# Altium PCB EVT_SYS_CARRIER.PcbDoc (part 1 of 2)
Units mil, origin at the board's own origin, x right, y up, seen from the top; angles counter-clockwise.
Board outline 3937.01 x 3149.61 mil, 4 copper layers (Top Layer, Mid-Layer 1, Mid-Layer 2, Bottom Layer), stack 63.036 mil thick; 92 components, 67 nets, 529 pads, 132 vias.
Unrouted connection lines stored in the file: 166.
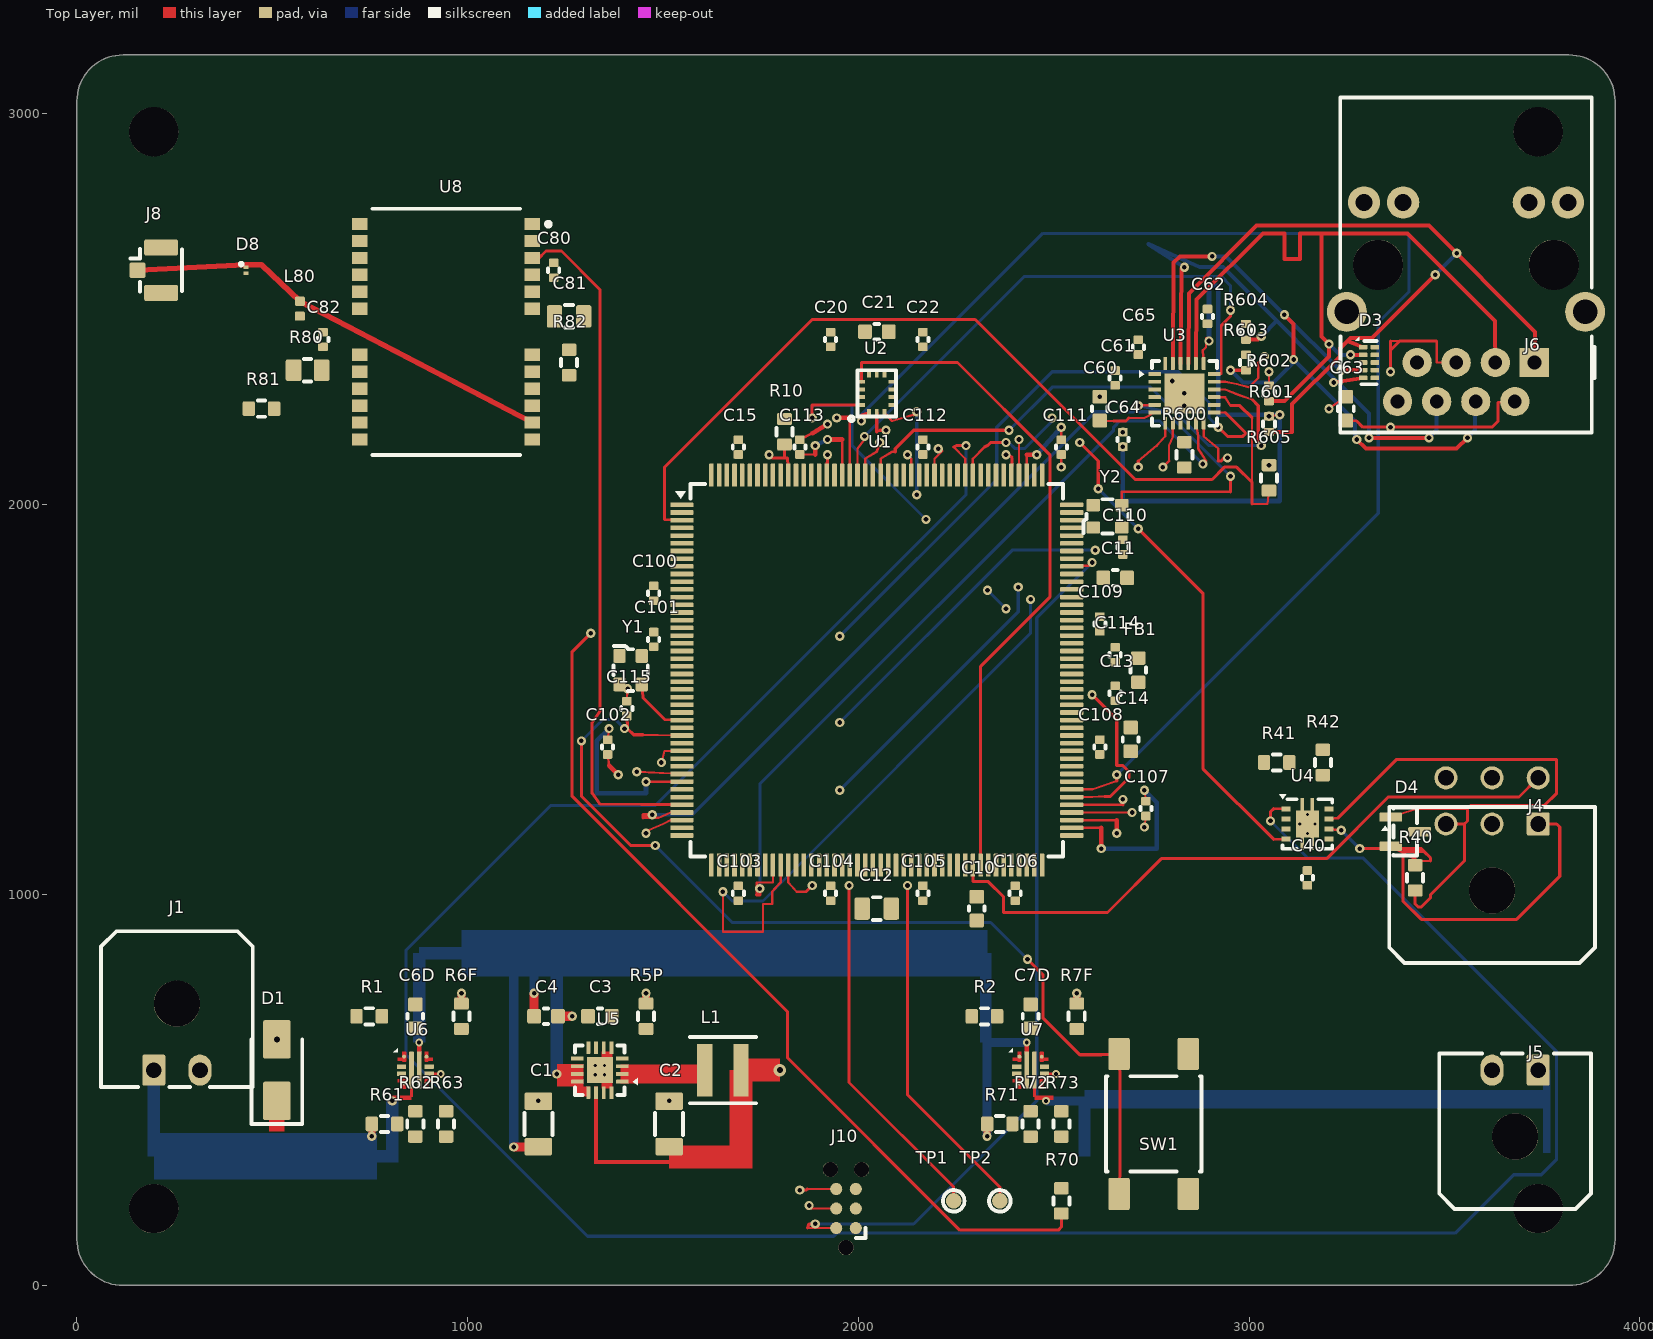
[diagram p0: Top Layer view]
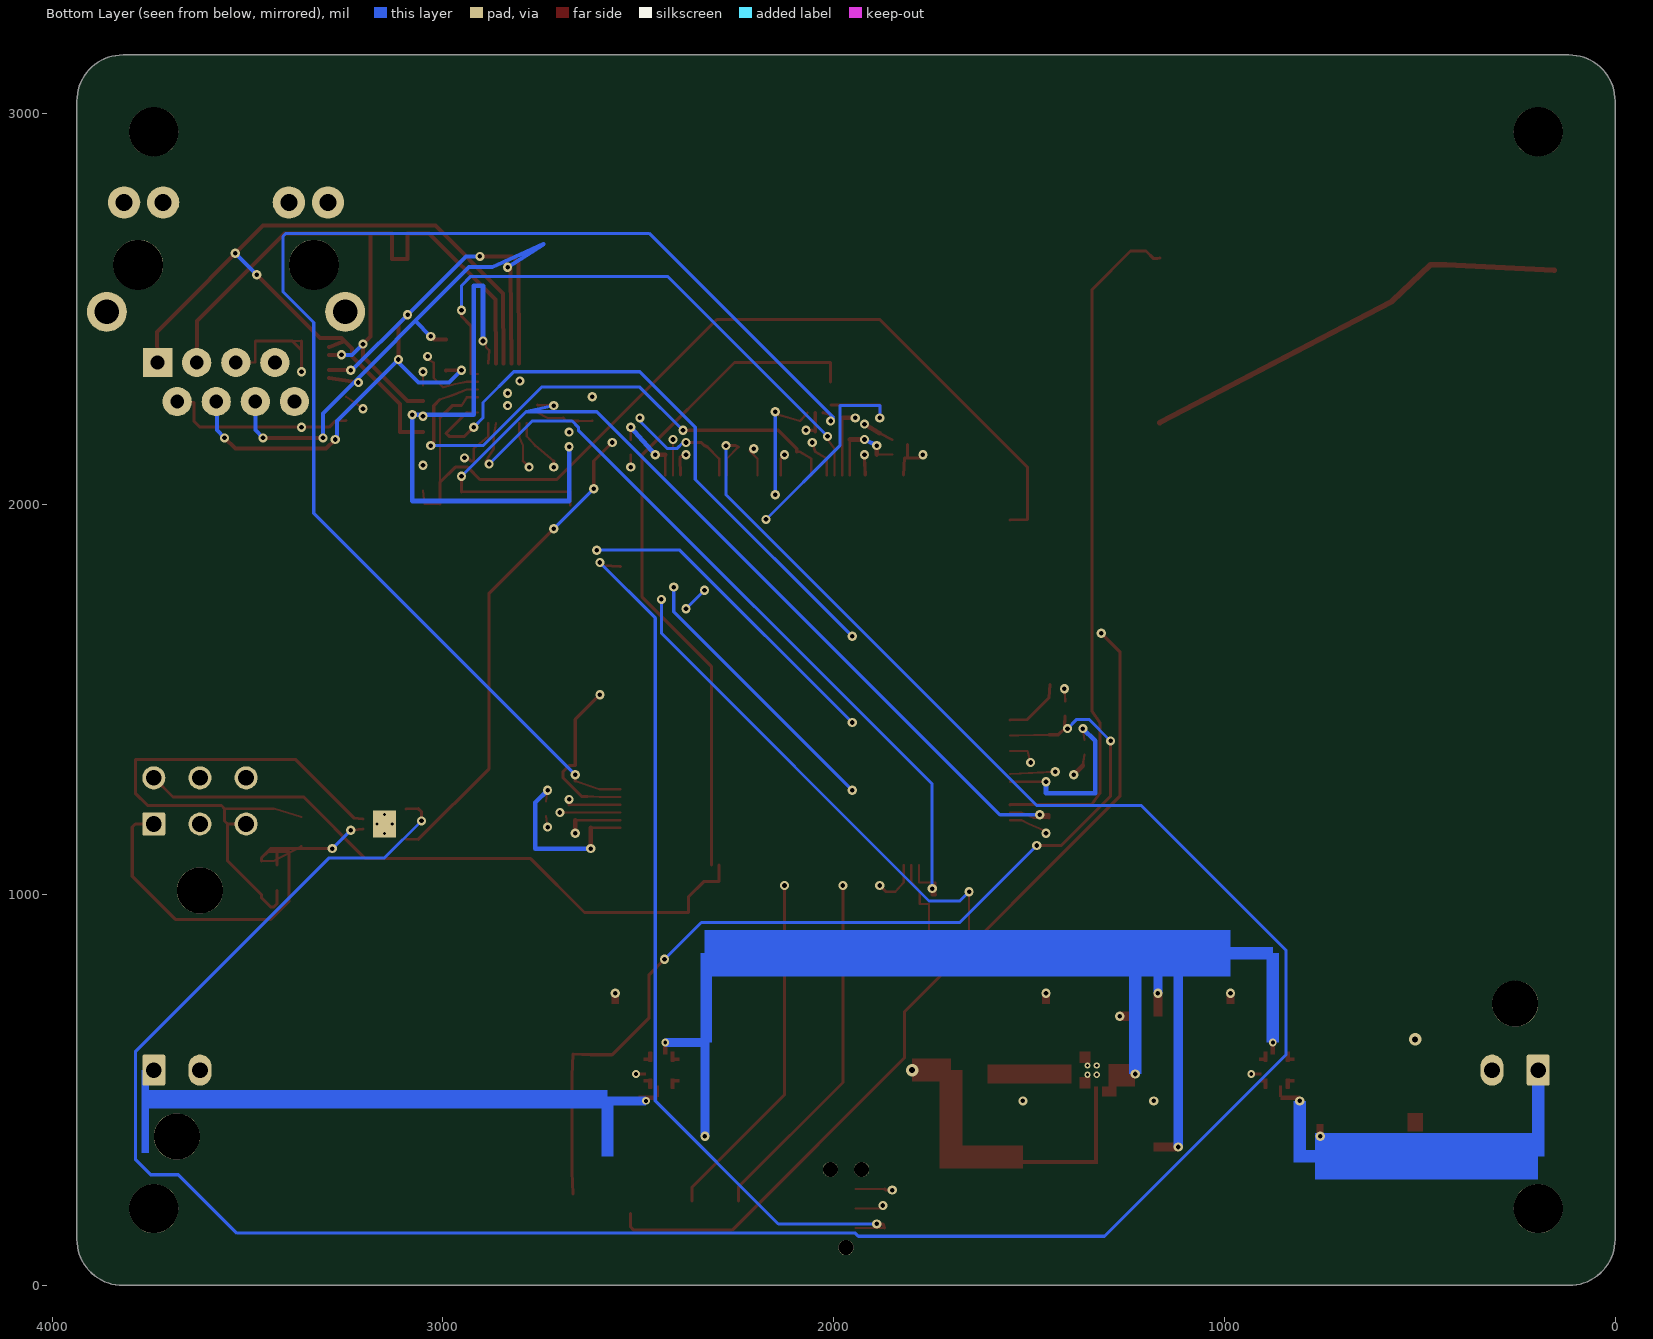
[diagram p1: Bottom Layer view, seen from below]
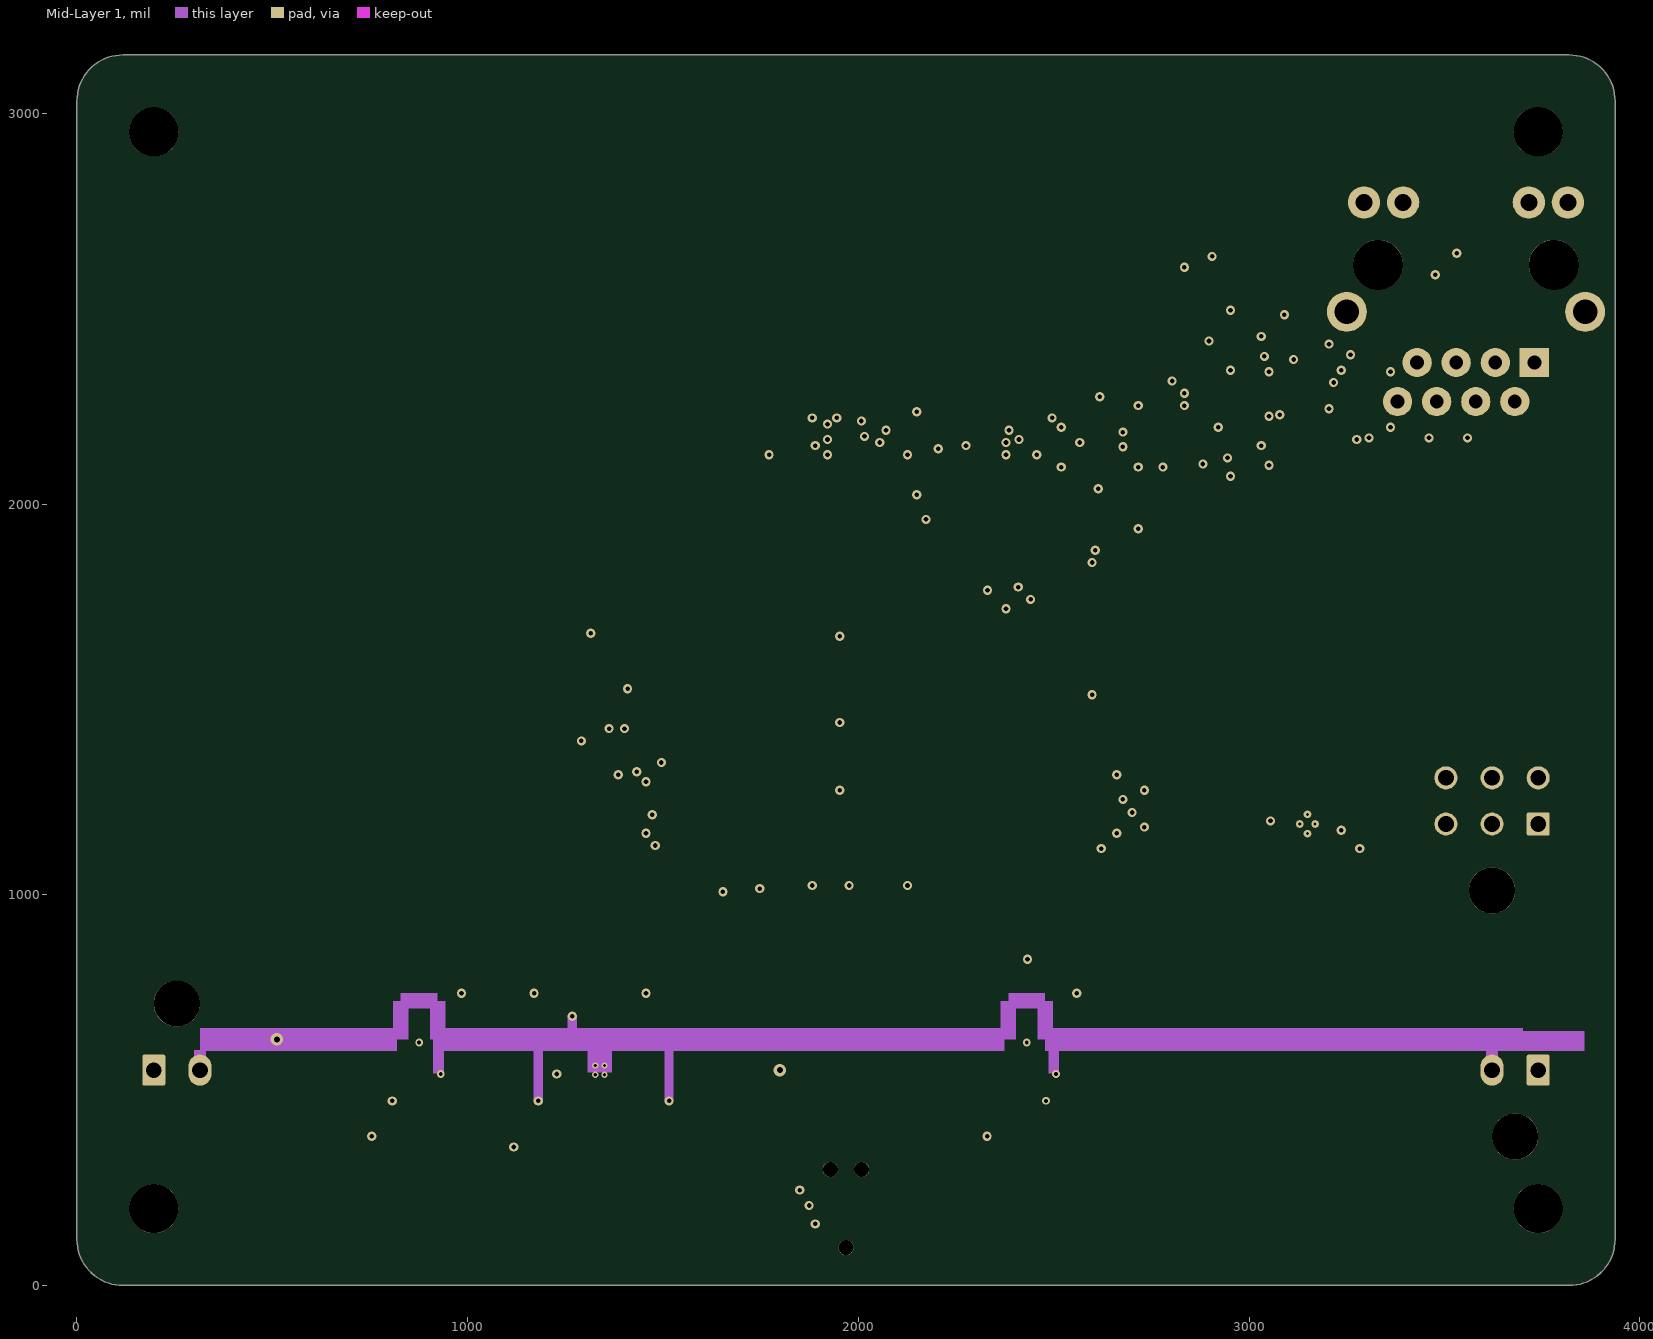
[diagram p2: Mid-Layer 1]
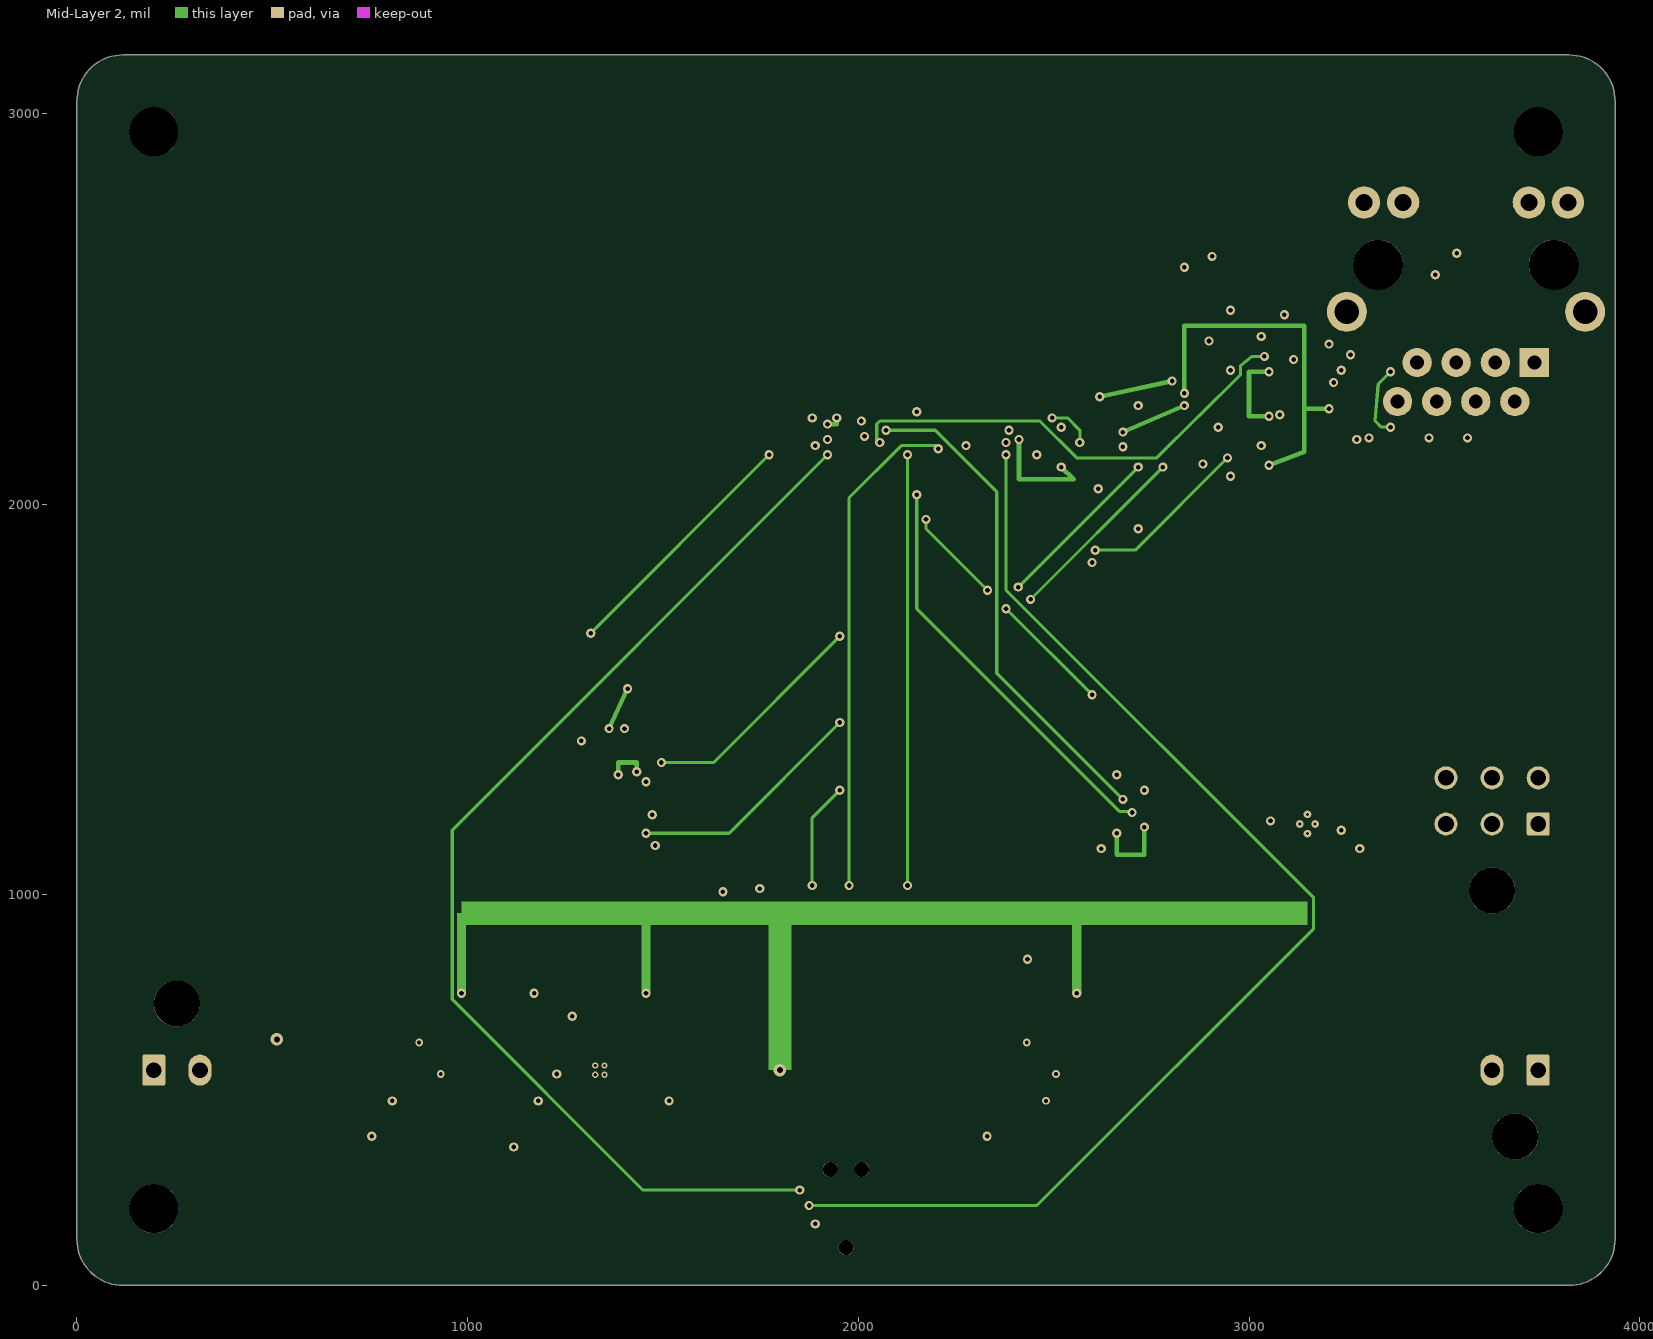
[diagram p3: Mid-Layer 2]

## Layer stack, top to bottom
Top Solder: solder mask 0.4, Solder Resist, Dk 3.5
Top Layer: signal copper 1.4
Dielectric 2: prepreg 7.0866, PP-006, Dk 4.2
Mid-Layer 1: signal copper 1.378
Dielectric 1: dielectric 43.3071, FR-4, Dk 4.2
Mid-Layer 2: signal copper 1.378
Dielectric 3: prepreg 7.0866, PP-006, Dk 4.2
Bottom Layer: signal copper 1.4
Bottom Solder: solder mask 0.4, Solder Resist, Dk 3.5

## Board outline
118.11,0 cw(c118.11,118.11) 0,118.11 0,3031.5 cw(c118.11,3031.5) 118.11,3149.61 3818.9,3149.61 cw(c3818.9,3031.5) 3937.01,3031.5 3937.01,118.11 cw(c3818.9,118.11) 3818.9,0

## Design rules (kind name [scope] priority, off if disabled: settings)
Clearance R_FINE_PITCH_CLEARANCE [(InComponent('U6') Or InComponent('U7') Or InComponent('D8')) vs (InComponent('U6') Or InComponent('U7') Or InComponent('D8'))] p1: gap=5.12 ignorepadtopadclearanceinfootprint=FALSE // Footprint-defined fine-pitch clearance; fabricator confirmation deferred
Clearance R_TIMING_TO_SW_CLEARANCE [InNetClass('NC_TIMING') vs InNet('BUCK_SW')] p2: gap=39.37 ignorepadtopadclearanceinfootprint=FALSE // EVT routing contract
Clearance R_ETH_MDI_CLEARANCE [InDifferentialPairClass('DP_ETH_MDI') vs Not InDifferentialPairClass('DP_ETH_MDI')] p3: gap=7.87 ignorepadtopadclearanceinfootprint=FALSE // EVT routing contract
Clearance R_GENERAL_CLEARANCE [All] p4: gap=7.87 ignorepadtopadclearanceinfootprint=FALSE // EVT routing contract
Clearance [All] p5: gap=10 ignorepadtopadclearanceinfootprint=FALSE
ComponentClearance [All] p1 off: gap=7.87 collisioncheckmode=3 verticalgap=7.87 showdistances=FALSE // Disabled: imported body extents are not assembly courtyards; see placement review evidence
DiffPairsRouting R_CAN_DIFF [InDifferentialPairClass('DP_CAN')] p1: maxlimit=11.81 minlimit=7.87 mostfreqgap=7.87 toplayer_minwidth=7.87 toplayer_maxwidth=11.81 toplayer_prefwidth=7.87 midlayer1_minwidth=7.87 midlayer1_maxwidth=11.81 midlayer1_prefwidth=7.87 midlayer2_minwidth=7.87 midlayer2_maxwidth=11.81 midlayer2_prefwidth=7.87 bottomlayer_minwidth=7.87 bottomlayer_maxwidth=11.81 bottomlayer_prefwidth=7.87 maxuncoupledlength=500 // EVT routing contract
DiffPairsRouting R_ETH_MDI_DIFF [InDifferentialPairClass('DP_ETH_MDI')] p2: maxlimit=7.87 minlimit=7.87 mostfreqgap=7.87 toplayer_minwidth=10.24 toplayer_maxwidth=10.24 toplayer_prefwidth=10.24 midlayer1_minwidth=10.24 midlayer1_maxwidth=10.24 midlayer1_prefwidth=10.24 midlayer2_minwidth=10.24 midlayer2_maxwidth=10.24 midlayer2_prefwidth=10.24 bottomlayer_minwidth=10.24 bottomlayer_maxwidth=10.24 bottomlayer_prefwidth=10.24 maxuncoupledlength=500 // EVT routing contract
DiffPairsRouting [All] p3: maxlimit=10 minlimit=10 mostfreqgap=10 toplayer_minwidth=15 toplayer_maxwidth=15 toplayer_prefwidth=15 midlayer1_minwidth=15 midlayer1_maxwidth=15 midlayer1_prefwidth=15 midlayer2_minwidth=15 midlayer2_maxwidth=15 midlayer2_prefwidth=15 bottomlayer_minwidth=15 bottomlayer_maxwidth=15 bottomlayer_prefwidth=15 maxuncoupledlength=500
HoleSize [All] p1: absolutevalues=TRUE maxlimit=129.92 minlimit=7.09 maxpercent=80.000 minpercent=20.000 // Standard PTH and 3.2/3.25mm mechanical holes
PolygonConnect [All] p1: connectstyle=Relief reliefconductorwidth=10 reliefentries=4 polygonreliefangle="90 Angle" airgapwidth=10
RoutingVias [All] p1: holewidth=28 width=50 viastyle="Through Hole" minholewidth=28 minwidth=50 maxholewidth=28 maxwidth=50
SolderMaskExpansion [All] p1: expansion=0 istentingtop=FALSE
Width R_3V3_TRUNK_WIDTH [InNet('3V3')] p1: maxlimit=118.11 minlimit=59.06 preferedwidth=59.06 // EVT routing contract
Width R_RADAR_12V_WIDTH [InNet('RADAR_12V')] p2: maxlimit=118.11 minlimit=59.06 preferedwidth=59.06
Width R_VIN_HIGH_CURRENT [InNet('VIN_RAW','VIN_PROTECTED')] p3: maxlimit=196.85 minlimit=118.11 preferedwidth=118.11
Width R_GNSS_RF_WIDTH [InNet('GNSS_RF')] p4: maxlimit=14.17 minlimit=14.17 preferedwidth=14.17
Width R_GENERAL_WIDTH [All] p5: maxlimit=19.68 minlimit=5.91 preferedwidth=7.87
27 further rules are at their usual default settings.

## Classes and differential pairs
net class NC_IMU_SPI: IMU_MISO IMU_MOSI IMU_NSS IMU_SCK
net class NC_RMII: ETH_50M ETH_CRS_DV ETH_MDC ETH_MDIO ETH_NRST ETH_RXD0 ETH_RXD1 ETH_TX_EN ETH_TXD0 ETH_TXD1
net class NC_TIMING: GNSS_PPS IMU_DRDY RADAR_REF
net class NC_CAN: RADAR_CANH RADAR_CANL
net class NC_GNSS_RF: GNSS_RF
net class NC_ETH_MDI: ETH_RXN ETH_RXP ETH_TXN ETH_TXP
net class NC_POWER_3V3: 3V3 VDDA_FILTERED
net class NC_POWER_12V: RADAR_12V VIN_PROTECTED VIN_RAW
differential pair class DP_CAN: DP_CAN
differential pair class DP_ETH_MDI: DP_ETH_RX DP_ETH_TX
component class 70_DEBUG_BOOT: R70 SW1
component class 60_ETHERNET: C60 C61 C62 C63 C64 C65 D3 J6 R600 R601 R602 R603 R604 R605 U3 Y2
component class 50_RADAR_IO_CAN: C40 D4 J4 J5 R40 R41 R42 U4
component class 40_IMU: C20 C21 C22 U2
component class 30_TIME_GNSS: C80 C81 C82 D8 J8 L80 R80 R81 R82 U8
component class 20_MCU_CORE: C10 C11 C12 C13 C14 C15 C100 C101 C102 C103 C104 C105 C106 C107 C108 C109 C110 C111 C112 C113 C114 C115 FB1 J10 R10 TP1 TP2 U1 Y1
component class 10_POWER_INPUT: C1 C2 C3 C4 C6D C7D D1 J1 L1 R1 R2 R5P R6F R7F R61 R62 R63 R71 R72 R73 U5 U6 U7
differential pair DP_CAN: +RADAR_CANH -RADAR_CANL
differential pair DP_ETH_RX: +ETH_RXP -ETH_RXN
differential pair DP_ETH_TX: +ETH_TXP -ETH_TXN

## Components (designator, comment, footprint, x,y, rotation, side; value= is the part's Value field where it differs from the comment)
C1 "10uF/25V" C_1206_3216Metric 1181.1,413.39 r90 top
C2 "22uF/6.3V" C_1206_3216Metric 1515.75,413.39 r90 top
C3 "3.3nF" C_0603_1608Metric 1338.58,688.98 r0 top
C4 "100nF/25V" C_0603_1608Metric 1200.79,688.98 r0 top
C6D "3.3nF" C_0603_1608Metric 866.14,688.98 r90 top
C7D "3.3nF" C_0603_1608Metric 2440.94,688.98 r90 top
C10 "2.2uF" C_0603_1608Metric 2303.15,964.57 r90 top
C11 "2.2uF" C_0603_1608Metric 2657.48,1811.02 r0 top
C12 "4.7uF" C_0805_2012Metric 2047.24,964.57 r0 top
C13 "100nF" C_0402_1005Metric 2657.48,1515.75 r90 top
C14 "1uF" C_0603_1608Metric 2696.85,1397.64 r90 top
C15 "100nF" C_0402_1005Metric 1692.91,2145.67 r90 top
C20 "100nF" C_0402_1005Metric 1929.13,2421.26 r90 top
C21 "2.2uF" C_0603_1608Metric 2047.24,2440.94 r0 top
C22 "10nF" C_0402_1005Metric 2165.35,2421.26 r90 top
C40 "100nF" C_0402_1005Metric 3149.61,1043.31 r90 top
C60 "1uF" C_0603_1608Metric 2618.11,2244.09 r90 top
C61 "470pF C0G" C_0402_1005Metric 2657.48,2322.83 r90 top
C62 "100nF" C_0402_1005Metric 2893.7,2480.32 r90 top
C63 "22nF C0G" C_0603_1608Metric 3248.03,2244.09 r90 top
C64 "100nF" C_0402_1005Metric 2677.16,2165.35 r90 top
C65 "100nF" C_0402_1005Metric 2716.54,2401.57 r90 top
C80 "100nF" C_0402_1005Metric 1220.47,2598.43 r90 top
C81 "10uF" C_0805_2012Metric 1259.84,2480.32 r0 top
C82 "100nF DNP_OPTION" C_0402_1005Metric 629.92,2421.26 r90 top
C100 "100nF VDD" C_0402_1005Metric 1476.38,1771.65 r90 top
C101 "100nF VDD" C_0402_1005Metric 1476.38,1653.54 r90 top
C102 "100nF VDD" C_0402_1005Metric 1358.27,1377.95 r90 top
C103 "100nF VDD" C_0402_1005Metric 1692.91,1003.94 r90 top
C104 "100nF VDD" C_0402_1005Metric 1929.13,1003.94 r90 top
C105 "100nF VDD" C_0402_1005Metric 2165.35,1003.94 r90 top
C106 "100nF VDD" C_0402_1005Metric 2401.57,1003.94 r90 top
C107 "100nF VDD" C_0402_1005Metric 2736.22,1220.47 r90 top
C108 "100nF VDD" C_0402_1005Metric 2618.11,1377.95 r90 top
C109 "100nF VDD" C_0402_1005Metric 2618.11,1692.91 r90 top
C110 "100nF VDD" C_0402_1005Metric 2677.17,1889.76 r90 top
C111 "100nF VDD" C_0402_1005Metric 2519.69,2145.67 r90 top
C112 "100nF VDD" C_0402_1005Metric 2165.35,2145.67 r90 top
C113 "100nF VDD" C_0402_1005Metric 1850.39,2145.67 r90 top
C114 "100nF VDD33_USB" C_0402_1005Metric 2657.48,1614.17 r90 top
C115 "100nF NRST" C_0402_1005Metric 1407.48,1476.38 r90 top
D1 "SMAJ15CA" D_SMA 511.81,551.18 r90 top
D3 "TPD4E05U06DQAR" USON-10_2.5x1.0mm_P0.5mm 3307.09,2362.2 r0 top
D4 "ESD2CANFD24-Q1" SOT-23 3399.61,1161.42 r0 top
D8 "ESD0P2RF-02LS" ESD0P2RF-02LS_PG-TSSLP-2-1 433.07,2598.43 r0 top
FB1 "BLM18BD601SH1" L_0603_1608Metric 2716.54,1574.8 r90 top
J1 "12V_IN" Molex_43650-0200_RA_THT_2P#1 196.85,551.18 r0 top
J4 "RADAR_IO" Molex_43045-0600_RA_THT_6P 3740.16,1181.1 r180 top
J5 "RADAR_PWR" Molex_43650-0200_RA_THT_2P#2 3740.16,551.18 r180 top
J6 "SI-60182-F" RJ45_Bel_SI-60062-F 3730.32,2362.2 r180 top
J8 "GNSS_UFL" Hirose_UFL_R_SMT_K 196.85,2598.43 r0 top
J10 "TC2030_SWD" TagConnect_TC2030_NL 1968.5,196.85 r90 top
L1 "2.2uH" Coilcraft_XFL4020_4x4 1653.54,551.18 r0 top
L80 "27nH DNP_OPTION" L_0402_1005Metric 570.87,2500 r90 top
R1 "665R 1%" R_0603_1608Metric 748.03,688.98 r0 top
R2 "1.05k 1%" R_0603_1608Metric 2322.83,688.98 r0 top
R5P "100k 1% PG_PU" R_0603_1608Metric 1456.69,688.98 r90 top
R6F "10k 1% FLT_PU" R_0603_1608Metric 984.25,688.98 r90 top
R7F "10k 1% FLT_PU" R_0603_1608Metric 2559.06,688.98 r90 top
R10 "10k 1%" R_0603_1608Metric 1811.02,2185.04 r90 top
R40 "120R 1% DNP_DEFAULT" R_0603_1608Metric 3425.2,1043.31 r90 top
R41 "10k 1% STB_PD" R_0603_1608Metric 3070.87,1338.58 r0 top
R42 "10k 1% SHDN_PD" R_0603_1608Metric 3188.98,1338.58 r90 top
R61 "470k 1%" R_0603_1608Metric 787.4,413.39 r0 top
R62 "36.0k 1%" R_0603_1608Metric 866.14,413.39 r90 top
R63 "41.2k 1%" R_0603_1608Metric 944.88,413.39 r90 top
R70 "0R DNP_BOOT_OVERRIDE" R_0603_1608Metric 2519.68,216.54 r90 top
R71 "470k 1%" R_0603_1608Metric 2362.2,413.39 r0 top
R72 "16.9k 1%" R_0603_1608Metric 2440.94,413.39 r90 top
R73 "43.7k 1%" R_0603_1608Metric 2519.68,413.39 r90 top
R80 "10R 0.25W DNP_OPTION" R_0805_2012Metric 590.55,2342.52 r0 top
R81 "100k 1% VUSB_PD" R_0603_1608Metric 472.44,2244.09 r0 top
R82 "0R V_BCKP" R_0603_1608Metric 1259.84,2362.2 r90 top
R600 "12.1k 1%" R_0603_1608Metric 2834.65,2125.98 r90 top
R601 "49.9R 1%" R_0402_1005Metric 3051.18,2204.72 r90 top
R602 "49.9R 1%" R_0402_1005Metric 3051.18,2283.47 r90 top
R603 "49.9R 1%" R_0402_1005Metric 2992.13,2362.2 r90 top
R604 "49.9R 1%" R_0402_1005Metric 2992.13,2440.94 r90 top
R605 "10k 1% NRST_PD" R_0603_1608Metric 3051.18,2066.93 r90 top
SW1 "NRST" ESwitch_TL3301_GullWing_6x6 2755.91,314.96 r90 top
TP1 "DEBUG_TX" TestPoint_Pad_D1.0mm 2244.09,216.54 r0 top
TP2 "DEBUG_RX" TestPoint_Pad_D1.0mm 2362.2,216.54 r0 top
U1 "STM32H753IIT6" LQFP-176_24x24mm_P0.5mm 2047.24,1574.8 r0 top
U2 "ICM-42688-P" ICM-42688-P_LGA14_2.5x3mm_P0.5mm 2047.24,2283.46 r0 top
U3 "LAN8742Ai-CZ-TR" QFN-24-1EP_4x4mm_P0.5mm_EP2.6x2.6mm 2834.65,2283.46 r0 top
U4 "TCAN3404DRBRQ1" Texas_DRB0008A 3149.61,1181.1 r0 top
U5 "TPS62132RGTR_3V3" VQFN-16-1EP_3x3mm_P0.5mm_EP1.68x1.68mm 1338.58,551.18 r180 top
U6 "TPS259470ARPWR_SYS" TPS259470A_RPW0010A_VQFN-HR-10_2x2mm_P0.475mm 866.14,551.18 r0 top
U7 "TPS259470ARPWR_RADAR" TPS259470A_RPW0010A_VQFN-HR-10_2x2mm_P0.475mm 2440.94,551.18 r0 top
U8 "NEO-M9N-00B" NEO-M9N_LCC24_12.2x16mm 944.88,2440.94 r0 top
Y1 "ECS-2520S33-250-FN-TR" Oscillator_SMD_ECS_2520MV-xxx-xx-4Pin_2.5x2.0mm 1417.32,1574.8 r0 top
Y2 "ECS-2520S33-500-FN-TR" Oscillator_SMD_ECS_2520MV-xxx-xx-4Pin_2.5x2.0mm 2637.8,1968.5 r90 top

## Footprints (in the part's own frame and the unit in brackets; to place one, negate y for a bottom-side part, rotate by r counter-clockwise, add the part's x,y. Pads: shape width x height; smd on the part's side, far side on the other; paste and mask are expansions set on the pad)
C_0402_1005Metric [mm]
  rrect25% 0.56x0.62 smd: 1(-0.48,0) 2(0.48,0)
  silkscreen extent -0.11,-0.36 0.11,0.36
C_0603_1608Metric [mm]
  rrect25% 0.9x0.95 smd: 1(-0.775,0) 2(0.775,0)
  silkscreen extent -0.14,-0.51 0.14,0.51
C_0805_2012Metric [mm]
  rrect25% 1x1.45 smd: 1(-0.95,0) 2(0.95,0)
  silkscreen extent -0.26,-0.73 0.26,0.73
C_1206_3216Metric [mm]
  rrect22% 1.15x1.8 smd: 1(-1.475,0) 2(1.475,0)
  silkscreen extent -0.71,-0.91 0.71,0.91
Coilcraft_XFL4020_4x4 [mm]
  rect 0.98x3.4 smd: 1(-1.185,0) 2(1.185,0)
  silkscreen extent -2.15,-2.15 2.15,2.15
D_SMA [mm]
  rrect14% 2.5x1.8 smd: 1(-2,0) 2(2,0)
  silkscreen extent -3.51,-1.65 2,1.65
ESD0P2RF-02LS_PG-TSSLP-2-1 [mm]
  rect 0.32x0.24 smd: 1(0,0.19) 2(0,-0.19)
  silkscreen extent -0.4,0.32 -0.24,0.48
ESwitch_TL3301_GullWing_6x6 [mil]
Hirose_UFL_R_SMT_K [mm]
  rrect25% 1.05x1 smd: 1(-1.05,0)
  rrect24% 2.2x1.05 smd: 2(0.475,-1.475) 2(0.475,1.475)
  silkscreen extent -1.52,-1.4 1.84,1.4
ICM-42688-P_LGA14_2.5x3mm_P0.5mm [mm]
  rect 0.475x0.25 smd: 1(-1.012,-0.75) 2(-1.012,-0.25) 3(-1.012,0.25) 4(-1.012,0.75) 8(1.012,0.75) 9(1.012,0.25) 10(1.012,-0.25) 11(1.012,-0.75)
  rect 0.25x0.475 smd: 5(-0.5,1.262) 6(0,1.262) 7(0.5,1.262) 12(0.5,-1.262) 13(0,-1.262) 14(-0.5,-1.262)
  silkscreen extent -1.8,-1.8 1.25,1.5
L_0402_1005Metric [mm]
  rrect25% 0.59x0.64 smd: 1(-0.485,0) 2(0.485,0)
L_0603_1608Metric [mm]
  rrect25% 0.875x0.95 smd: 1(-0.787,0) 2(0.787,0)
  silkscreen extent -0.16,-0.51 0.16,0.51
LQFP-176_24x24mm_P0.5mm [mm]
  rrect25% 1.5x0.3 smd: 1(-12.675,10.75) 2(-12.675,10.25) 3(-12.675,9.75) 4(-12.675,9.25) 5(-12.675,8.75) 6(-12.675,8.25) 7(-12.675,7.75) 8(-12.675,7.25) 9(-12.675,6.75) 10(-12.675,6.25) 11(-12.675,5.75) 12(-12.675,5.25) 13(-12.675,4.75) 14(-12.675,4.25) 15(-12.675,3.75) 16(-12.675,3.25) 17(-12.675,2.75) 18(-12.675,2.25) 19(-12.675,1.75) 20(-12.675,1.25) 21(-12.675,0.75) 22(-12.675,0.25) 23(-12.675,-0.25) 24(-12.675,-0.75) 25(-12.675,-1.25) 26(-12.675,-1.75) 27(-12.675,-2.25) 28(-12.675,-2.75) 29(-12.675,-3.25) 30(-12.675,-3.75) 31(-12.675,-4.25) 32(-12.675,-4.75) 33(-12.675,-5.25) 34(-12.675,-5.75) 35(-12.675,-6.25) 36(-12.675,-6.75) 37(-12.675,-7.25) 38(-12.675,-7.75) 39(-12.675,-8.25) 40(-12.675,-8.75) 41(-12.675,-9.25) 42(-12.675,-9.75) 43(-12.675,-10.25) 44(-12.675,-10.75) 89(12.675,-10.75) 90(12.675,-10.25) 91(12.675,-9.75) 92(12.675,-9.25) 93(12.675,-8.75) 94(12.675,-8.25) 95(12.675,-7.75) 96(12.675,-7.25) 97(12.675,-6.75) 98(12.675,-6.25) 99(12.675,-5.75) 100(12.675,-5.25) 101(12.675,-4.75) 102(12.675,-4.25) 103(12.675,-3.75) 104(12.675,-3.25) 105(12.675,-2.75) 106(12.675,-2.25) 107(12.675,-1.75) 108(12.675,-1.25) 109(12.675,-0.75) 110(12.675,-0.25) 111(12.675,0.25) 112(12.675,0.75) 113(12.675,1.25) 114(12.675,1.75) 115(12.675,2.25) 116(12.675,2.75) 117(12.675,3.25) 118(12.675,3.75) 119(12.675,4.25) 120(12.675,4.75) 121(12.675,5.25) 122(12.675,5.75) 123(12.675,6.25) 124(12.675,6.75) 125(12.675,7.25) 126(12.675,7.75) 127(12.675,8.25) 128(12.675,8.75) 129(12.675,9.25) 130(12.675,9.75) 131(12.675,10.25) 132(12.675,10.75)
  rrect25% 0.3x1.5 smd: 45(-10.75,-12.675) 46(-10.25,-12.675) 47(-9.75,-12.675) 48(-9.25,-12.675) 49(-8.75,-12.675) 50(-8.25,-12.675) 51(-7.75,-12.675) 52(-7.25,-12.675) 53(-6.75,-12.675) 54(-6.25,-12.675) 55(-5.75,-12.675) 56(-5.25,-12.675) 57(-4.75,-12.675) 58(-4.25,-12.675) 59(-3.75,-12.675) 60(-3.25,-12.675) 61(-2.75,-12.675) 62(-2.25,-12.675) 63(-1.75,-12.675) 64(-1.25,-12.675) 65(-0.75,-12.675) 66(-0.25,-12.675) 67(0.25,-12.675) 68(0.75,-12.675) 69(1.25,-12.675) 70(1.75,-12.675) 71(2.25,-12.675) 72(2.75,-12.675) 73(3.25,-12.675) 74(3.75,-12.675) 75(4.25,-12.675) 76(4.75,-12.675) 77(5.25,-12.675) 78(5.75,-12.675) 79(6.25,-12.675) 80(6.75,-12.675) 81(7.25,-12.675) 82(7.75,-12.675) 83(8.25,-12.675) 84(8.75,-12.675) 85(9.25,-12.675) 86(9.75,-12.675) 87(10.25,-12.675) 88(10.75,-12.675) 133(10.75,12.675) 134(10.25,12.675) 135(9.75,12.675) 136(9.25,12.675) 137(8.75,12.675) 138(8.25,12.675) 139(7.75,12.675) 140(7.25,12.675) 141(6.75,12.675) 142(6.25,12.675) 143(5.75,12.675) 144(5.25,12.675) 145(4.75,12.675) 146(4.25,12.675) 147(3.75,12.675) 148(3.25,12.675) 149(2.75,12.675) 150(2.25,12.675) 151(1.75,12.675) 152(1.25,12.675) 153(0.75,12.675) 154(0.25,12.675) 155(-0.25,12.675) 156(-0.75,12.675) 157(-1.25,12.675) 158(-1.75,12.675) 159(-2.25,12.675) 160(-2.75,12.675) 161(-3.25,12.675) 162(-3.75,12.675) 163(-4.25,12.675) 164(-4.75,12.675) 165(-5.25,12.675) 166(-5.75,12.675) 167(-6.25,12.675) 168(-6.75,12.675) 169(-7.25,12.675) 170(-7.75,12.675) 171(-8.25,12.675) 172(-8.75,12.675) 173(-9.25,12.675) 174(-9.75,12.675) 175(-10.25,12.675) 176(-10.75,12.675)
  silkscreen extent -13.09,-12.11 12.11,12.11
Molex_43045-0600_RA_THT_6P [mil]
Molex_43650-0200_RA_THT_2P#1 [mm]
  rrect17% 1.5x2.02 hole 1.02: 1(0,0)
  rrect100% 1.5x2.02 hole 1.02: 2(3,0)
  round 3 hole 3: Un1(1.5,4.32)
  silkscreen extent -3.43,-1.09 6.44,9.03
Molex_43650-0200_RA_THT_2P#2 [mm]
NEO-M9N_LCC24_12.2x16mm [mm]
  rect 1x0.8 smd: 1(5.6,7) 2(5.6,5.9) 3(5.6,4.8) 4(5.6,3.7) 5(5.6,2.6) 6(5.6,1.5) 7(5.6,-1.5) 8(5.6,-2.6) 9(5.6,-3.7) 10(5.6,-4.8) 11(5.6,-5.9) 12(5.6,-7) 13(-5.6,-7) 14(-5.6,-5.9) 15(-5.6,-4.8) 16(-5.6,-3.7) 17(-5.6,-2.6) 18(-5.6,-1.5) 19(-5.6,1.5) 20(-5.6,2.6) 21(-5.6,3.7) 22(-5.6,4.8) 23(-5.6,5.9) 24(-5.6,7)
  silkscreen extent -4.8,-8 6.8,8
Oscillator_SMD_ECS_2520MV-xxx-xx-4Pin_2.5x2.0mm [mm]
  rrect25% 0.8x0.9 smd: 1(-0.725,0.925) 2(-0.725,-0.925) 3(0.725,-0.925) 4(0.725,0.925)
  silkscreen extent -1.11,-1.36 1.11,1.56
QFN-24-1EP_4x4mm_P0.5mm_EP2.6x2.6mm [mm]
  rrect25% 0.825x0.25 smd: 1(-1.937,1.25) 2(-1.937,0.75) 3(-1.937,0.25) 4(-1.937,-0.25) 5(-1.937,-0.75) 6(-1.937,-1.25) 13(1.937,-1.25) 14(1.937,-0.75) 15(1.937,-0.25) 16(1.937,0.25) 17(1.937,0.75) 18(1.937,1.25)
  rrect25% 0.25x0.825 smd: 7(-1.25,-1.937) 8(-0.75,-1.937) 9(-0.25,-1.937) 10(0.25,-1.937) 11(0.75,-1.937) 12(1.25,-1.937) 19(1.25,1.937) 20(0.75,1.937) 21(0.25,1.937) 22(-0.25,1.937) 23(-0.75,1.937) 24(-1.25,1.937)
  rect 2.6x2.6 smd: 25(0,0)
  rrect24% 1.05x1.05 on Top Paste: Un1(-0.65,0.65) Un2(-0.65,-0.65) Un3(0.65,0.65) Un4(0.65,-0.65)
  silkscreen extent -2.94,-2.11 2.11,2.11
R_0402_1005Metric [mm]
  rrect25% 0.54x0.64 smd: 1(-0.51,0) 2(0.51,0)
  silkscreen extent -0.15,-0.38 0.15,0.38
R_0603_1608Metric [mm]
  rrect25% 0.8x0.95 smd: 1(-0.825,0) 2(0.825,0)
  silkscreen extent -0.24,-0.52 0.24,0.52
R_0805_2012Metric [mm]
  rrect24% 1.025x1.4 smd: 1(-0.913,0) 2(0.913,0)
  silkscreen extent -0.23,-0.73 0.23,0.73
RJ45_Bel_SI-60062-F [mil]
SOT-23 [mil]
TagConnect_TC2030_NL [mil]
  round 31 smd: 1(-50,-25) 2(-50,25) 3(0,-25) 4(0,25) 5(50,-25) 6(50,25)
  round 39 hole 39: Un1(-100,0) Un2(100,40) Un3(100,-40)
  silkscreen extent -75,-50 -50,-25
TestPoint_Pad_D1.0mm [mm]
  round 1 smd: 1(0,0)
  silkscreen extent -0.7,-0.7 0.7,0.7
Texas_DRB0008A [mm]
  rrect16% 0.6x0.31 smd: 1(-1.4,0.975) 2(-1.4,0.325) 3(-1.4,-0.325) 4(-1.4,-0.975) 5(1.4,-0.975) 6(1.4,-0.325) 7(1.4,0.325) 8(1.4,0.975)
  round 0.5 hole 0.2: 9(-0.5,0) 9(0,-0.625) 9(0,0.625) 9(0.5,0)
  rrect22% 0.23x1.025 smd: 9(-0.325,-1.188) 9(-0.325,1.188) 9(0.325,-1.188) 9(0.325,1.188)
  rrect3% 1.5x1.75 smd: 9(0,0)
  rrect3% 1.5x1.75 smd far side: 9(0,0)
  rrect22% 0.23x0.725 on Top Paste: Un1(-0.325,1.337) Un2(-0.325,-1.337) Un4(0.325,1.337) Un5(0.325,-1.337)
  rrect4% 1.34x1.55 on Top Paste: Un3(0,0)
  silkscreen extent -1.85,-1.61 1.61,1.94
TPS259470A_RPW0010A_VQFN-HR-10_2x2mm_P0.475mm [mm]
  round 0.25 smd: 1(-0.725,0.875) 4(-0.725,-0.875) 7(0.725,-0.875) 10(0.725,0.875)
  rrect17% 0.6x0.3 smd: 2(-0.9,0.225) 3(-0.9,-0.225) 8(0.9,-0.225) 9(0.9,0.225)
  rrect17% 0.3x2.4 smd: 5(-0.25,0) 6(0.25,0)
  rrect17% 0.3x1.05 on Top Paste: Un1(-0.25,0.675) Un2(-0.25,-0.675) Un3(0.25,0.675) Un4(0.25,-0.675)
  Top Layer region: 0.8,0.8 1.15,0.8 1.15,0.6 0.65,0.6 0.65,1.15 0.8,1.15
  Top Layer region: 0.819,1.196 0.835,1.185 0.846,1.169 0.85,1.15 0.85,0.6 0.846,0.581 0.835,0.565 0.819,0.554 0.8,0.55 0.65,0.55 0.631,0.554 0.615,0.565 0.604,0.581 0.6,0.6 0.6,1.15 0.604,1.169 0.615,1.185 0.631,1.196 0.65,1.2 0.8,1.2
  Top Layer region: 1.15,-0.8 0.8,-0.8 0.8,-1.15 0.65,-1.15 0.65,-0.6 1.15,-0.6
  Top Layer region: 0.819,-0.554 0.835,-0.565 0.846,-0.581 0.85,-0.6 0.85,-1.15 0.846,-1.169 0.835,-1.185 0.819,-1.196 0.8,-1.2 0.65,-1.2 0.631,-1.196 0.615,-1.185 0.604,-1.169 0.6,-1.15 0.6,-0.6 0.604,-0.581 0.615,-0.565 0.631,-0.554 0.65,-0.55 0.8,-0.55
  Top Layer region: -0.65,-1.15 -0.8,-1.15 -0.8,-0.8 -1.15,-0.8 -1.15,-0.6 -0.65,-0.6
  Top Layer region: -0.631,-0.554 -0.615,-0.565 -0.604,-0.581 -0.6,-0.6 -0.6,-1.15 -0.604,-1.169 -0.615,-1.185 -0.631,-1.196 -0.65,-1.2 -0.8,-1.2 -0.819,-1.196 -0.835,-1.185 -0.846,-1.169 -0.85,-1.15 -0.85,-0.6 -0.846,-0.581 -0.835,-0.565 -0.819,-0.554 -0.8,-0.55 -0.65,-0.55
  Top Layer region: -0.65,0.6 -1.15,0.6 -1.15,0.8 -0.8,0.8 -0.8,1.15 -0.65,1.15
  Top Layer region: -0.631,1.196 -0.615,1.185 -0.604,1.169 -0.6,1.15 -0.6,0.6 -0.604,0.581 -0.615,0.565 -0.631,0.554 -0.65,0.55 -0.8,0.55 -0.819,0.554 -0.835,0.565 -0.846,0.581 -0.85,0.6 -0.85,1.15 -0.846,1.169 -0.835,1.185 -0.819,1.196 -0.8,1.2 -0.65,1.2
  silkscreen extent -1.43,1.15 -1.15,1.43
USON-10_2.5x1.0mm_P0.5mm [mm]
  rrect25% 0.55x0.3 smd: 1(-0.385,1) 2(-0.385,0.5) 3(-0.385,0) 4(-0.385,-0.5) 5(-0.385,-1) 6(0.385,-1) 7(0.385,-0.5) 8(0.385,0) 9(0.385,0.5) 10(0.385,1)
  silkscreen extent -0.9,-1.41 0.5,1.69
VQFN-16-1EP_3x3mm_P0.5mm_EP1.68x1.68mm [mm]
  rrect25% 0.825x0.25 smd: 1(-1.462,0.75) 2(-1.462,0.25) 3(-1.462,-0.25) 4(-1.462,-0.75) 9(1.462,-0.75) 10(1.462,-0.25) 11(1.462,0.25) 12(1.462,0.75)
  rrect25% 0.25x0.825 smd: 5(-0.75,-1.462) 6(-0.25,-1.462) 7(0.25,-1.462) 8(0.75,-1.462) 13(0.75,1.462) 14(0.25,1.462) 15(-0.25,1.462) 16(-0.75,1.462)
  rect 1.68x1.68 smd: 17(0,0)
  rrect25% 0.68x0.68 on Top Paste: Un1(-0.42,0.42) Un2(-0.42,-0.42) Un3(0.42,0.42) Un4(0.42,-0.42)
  silkscreen extent -2.47,-1.61 1.61,1.61

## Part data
C1: library part C, MPN=10uF_25V_X7R
C2: library part C, MPN=22uF_6.3V_X7R
C3 C6D C7D: library part C, MPN=3.3nF_X7R
C4: library part C, MPN=100nF_25V_X7R
C10 C11 C21: library part C, MPN=2.2uF_6.3V_X7R
C12: library part C, MPN=4.7uF_6.3V_X7R
C13 C15 C20 C40 C62 C64 C65 C100 C101 C102 C103 C104 C105 C106 C107 C108 C109 C110 C111 C112 C113 C114 C115: library part C, MPN=100nF_6.3V_X7R
C14 C60: library part C, MPN=1uF_6.3V_X7R
C22: library part C, MPN=10nF_6.3V_X7R
C61: library part C, MPN=470pF_C0G
C63: library part C, MPN=22nF_C0G
C80 C82: library part C, MPN=100nF_16V_X7R
C81: library part C, MPN=10uF_6.3V_X7R
D1 D8: library part D_TVS
D4: library part ESD2CANFD24DBZRQ1
FB1: library part L_Ferrite
J1 J5: library part Conn_01x02, MPN=43650-0200
J4: library part Conn_01x06, MPN=43045-0600
J6: library part RJ45_Bel_SI-60062-F
J8: library part Conn_01x02, MPN=U.FL-R-SMT-K(800)
J10: library part Conn_01x06, MPN=TC2030-NL_TARGET
L1: library part L, MPN=XFL4020-222MEC
L80: library part L, MPN=27nH_0402
R1: library part R, MPN=665R_1%
R2: library part R, MPN=1.05k_1%
R5P R81: library part R, MPN=100k_1%
R6F R7F R10 R41 R42 R605: library part R, MPN=10k_1%
R40: library part R, MPN=120R_1%
R61 R71: library part R, MPN=470k_1%
R62: library part R, MPN=36.0k_1%
R63: library part R, MPN=41.2k_1%
R70 R82: library part R, MPN=0R
R72: library part R, MPN=16.9k_1%
R73: library part R, MPN=43.7k_1%
R80: library part R, MPN=10R_0.25W
R600: library part R, MPN=12.1k_1%
R601 R602 R603 R604: library part R, MPN=49.9R_1%
SW1: library part SW_Push, MPN=TL3301NF160QG
TP1 TP2: library part TestPoint
U1: library part STM32H753IITx
U3: library part LAN8742A
U5: library part TPS62132RGTR
U6 U7: library part TPS259470ARPWR
U8: library part NEO-M9N

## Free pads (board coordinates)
  rrect18% 55.12x82.68 smd: 1(2667.32,234.25) 1(2667.32,592.52) 2(2844.49,234.25) 2(2844.49,592.52)
  rrect25% 58.07x23.62 smd: 1(3362.7,1198.82) 2(3362.7,1124.02) 3(3436.52,1161.42)
  rect 74.8x74.8 hole 35.43: 1(3730.32,2362.2)
  rrect17% 59.06x79.53 hole 40.16: 1(3740.16,551.18)
  rrect17% 59.06x59.06 hole 40.16: 1(3740.16,1181.1)
  rrect100% 59.06x79.53 hole 40.16: 2(3622.05,551.18)
  round 59.06 hole 40.16: 2(3622.05,1181.1) 3(3503.94,1181.1) 4(3740.16,1299.21) 5(3622.05,1299.21) 6(3503.94,1299.21)
  round 74.8 hole 35.43: 2(3680.32,2262.2) 3(3630.32,2362.2) 4(3580.32,2262.2) 5(3530.32,2362.2) 6(3480.32,2262.2) 7(3430.32,2362.2) 8(3380.32,2262.2)
  round 125.98 hole 125.98 unplated: H1(196.85,196.85) H2(3740.16,196.85) H3(196.85,2952.76) H4(3740.16,2952.76)
  round 82.68 hole 43.31: L1(3816.14,2772.05) L2(3716.14,2772.05) L3(3394.49,2772.05) L4(3294.49,2772.05)
  round 102.36 hole 62.99: SH(3250.39,2492.13) SH(3860.24,2492.13)
  round 118.11 hole 118.11: Un1(3622.05,1011.02) Un1(3681.1,381.1)
  round 127.95 hole 127.95: Un1(3780.32,2612.2) Un2(3330.32,2612.2)

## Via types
v1: diameter 23.62, hole 11.81, Top Layer to Bottom Layer, 121 vias
v2: diameter 19.68, hole 9.84, Top Layer to Bottom Layer, 5 vias
v3: diameter 15.75, hole 7.87, Top Layer to Bottom Layer, 4 vias
v4: diameter 31.5, hole 15.75, Top Layer to Bottom Layer, 2 vias

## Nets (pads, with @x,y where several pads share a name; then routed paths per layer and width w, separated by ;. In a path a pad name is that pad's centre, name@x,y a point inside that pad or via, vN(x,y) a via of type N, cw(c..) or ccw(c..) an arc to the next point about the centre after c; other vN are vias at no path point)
3V3: C2.1 C12.1 C15.1 C20.1 C21.1 C22.1 C40.1 C61.1 C62.1 C64.1 C65.1 C80.1 C81.1 C100.1 C101.1 C102.1 C103.1 C104.1 C105.1 C106.1 C107.1 C108.1 C109.1 C110.1 C111.1 C112.1 C113.1 C114.1 FB1.1 J10.1 L1.2 R5P.2 R6F.2 R7F.2 R70.2 R82.2 R601.2 R602.2 R603.2 R604.2 U1.6 U1.15 U1.23 U1.36 U1.49 U1.62 U1.72 U1.82 U1.91 U1.103 U1.114 U1.127 U1.136 U1.149 U1.159 U1.171 U1.172 U2.5 U2.8 U3.1 U3.9 U3.19 U4.3 U5.14 U8.23 Y1.4 Y2.4 | length 3064.1
  Top Layer w5.91: C102.1@1358.27,1359.06 1362.2,1330.71 ; v1(1433.07,1314.96) U1.36@1548.23,1309.06 ; C113.1@1850.39,2126.77 1889.76,2126.77 ; U1.159@1958.66,2073.82 1958.66,2165.35 ; U1.136@2411.42,2073.82 v1(2411.42,2165.35) ; v1(2519.68,2094.49) C111.1@2519.69,2126.77 ; U1.91@2546.26,1190.94 2661.42,1190.94 ; v1(2732.28,1173.23) C107.1@2736.22,1201.57 ; U3.19@2883.86,2359.74 2881.89,2393.7 2889.76,2401.57 2889.76,2425.2 v1(2897.64,2417.32) ; v1(3051.18,2224.8) v1(3078.74,2228.35) ; R602.2@3051.18,2303.54 v1(3051.18,2338.58)
  Top Layer w11.81: 1362.2,1330.71 v1(1385.83,1307.09) ; 1889.76,2126.77 v1(1889.76,2149.61) ; v1(1921.26,2165.35) 1958.66,2165.35 ; v1(2661.42,1157.48) 2661.42,1190.94
  Mid-Layer 2 w11.81: v1(1385.83,1307.09) 1385.83,1338.58 1433.07,1338.58 v1(1433.07,1314.96) ; v1(2411.42,2165.35) 2411.42,2062.99 2551.18,2062.99 v1(2519.68,2094.49) ; v1(2661.42,1157.48) 2661.42,1102.36 2732.28,1102.36 v1(2732.28,1173.23) ; v1(3051.18,2224.8) 3000,2224.41 3000,2338.58 v1(3051.18,2338.58)
  Bottom Layer w11.81: v1(1889.76,2149.61) v1(1921.26,2165.35) ; v1(2677.16,2146.46) 2677.17,2007.87 3078.74,2007.87 v1(3078.74,2228.35) 2921.26,2228.35 2921.26,2559.06 2897.64,2559.06 v1(2897.64,2417.32)
  other v1: 984.25,748.03 1456.69,748.03 2559.06,748.03
  other v4: 1799.21,551.18
BOOT0: R10.1 R70.1 U1.166 | length 3081
  Top Layer w7.87: v1(1314.96,1669.29) 1267.72,1622.05 1267.72,1251.97 1818.9,700.79 1818.9,582.68 2259.84,141.73 2511.81,141.73 2519.68,149.61 R70.1@2519.68,184.06 ; v1(1771.65,2125.98) 1779.53,2118.11 1811.02,2118.11 ; U1.166@1820.87,2073.82 1818.9,2118.11 1803.15,2118.11 1811.02,2118.11 ; 1811.02,2118.11 R10.1@1811.02,2152.56 1811.02,2118.11
  Mid-Layer 2 w7.87: v1(1314.96,1669.29) v1(1771.65,2125.98)
BUCK_SW: L1.1 U5.1 U5.2 U5.3
CAN_RX: U1.142 U4.4 | length 1673.4
  Top Layer w5.91: U1.142@2293.31,2073.82 2293.31,2116.14 2322.83,2145.67
  Top Layer w7.87: 2322.83,2145.67 2330.71,2149.61 2338.58,2157.48 v1(2377.95,2157.48) ; v1(2566.93,2157.48) 2614.17,2110.24 v1(2614.17,2039.37) ; v1(2716.54,1937.01) 2881.89,1771.65 2881.89,1322.83 3062.99,1141.73 U4.4@3094.49,1142.72
  Mid-Layer 2 w7.87: v1(2496.06,2220.47) 2535.43,2220.47 2566.93,2188.98 v1(2566.93,2157.48)
  Bottom Layer w7.87: v1(2377.95,2157.48) 2385.83,2157.48 2401.57,2141.73 2425.2,2141.73 2496.06,2212.6 v1(2496.06,2220.47) ; v1(2614.17,2039.37) v1(2716.54,1937.01)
